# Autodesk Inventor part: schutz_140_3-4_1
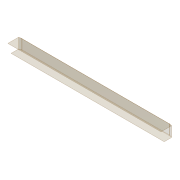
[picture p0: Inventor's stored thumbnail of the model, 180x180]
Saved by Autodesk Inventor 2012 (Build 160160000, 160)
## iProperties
Company: CAD-Verlag
Shininess: 64.0
Length Units: 11269
Angle Units: 11279
Time Units: 11290
Mass Units: 11283
Length Display Precision: 3
Angle Display Precision: 2
Compacted: True
Part Number: schutz_140_3-4_1
Document SubType Name: Sheet Metal
Created: 2004-09
Material: Standard
Designer: Greiling
Manufacturer: Standard
Standards Organization: Custom
Density: 1 g/cm^3
Sheet Metal Rule: Standard
Density: 0.0
Volumn: 0.0
Area: 0.0
PropertySet Name: Model Information
Control State: 0
Master: False
Checked Out: False
Author: Jürgen Kronas
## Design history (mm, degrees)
node "Fläche1"
  sketch "Skizze1"
    geometry: L1 (0, 168)-(2280, 168); L2 (2280, 168)-(2280, 0); L3 (2280, 0)-(0, 0); L4 (0, 0)-(0, 168); L5 (0, 218.4)-(0, -16.8) reference; L6 (-228, 0)-(2964, 0) reference; L7 (-228, 0)-(2964, 0) reference; L8 (0, -16.8)-(0, 218.4) reference; 1 further point
    constraints: 8 end point, 2 collinear, 2 parallel, 1 horizontal, 1 perpendicular
    dimensions: "d0" = 168 distance of L3.end L1.start; "d1" = 2280 distance of L1.start L1.end
sketch "Skizze2"
  geometry: L1 (0, 0)-(2280, 0) reference; L2 (0, -168)-(0, 0) reference; L3 (0, -10.718)-(40, 0); L4 (40, 0)-(0, 0); L5 (0, 0)-(0, -10.718); L6 (2280, 0)-(2280, -168) reference; L7 (2280, -10.718)-(2240, 0)
  constraints: 8 end point, 4 point on line, 2 collinear
  dimensions: "d31" = 40 distance from line of L3.end L2; "d32" = 15 deg angle of L3 L1; "d68" = 15 deg angle of L1 L7; "d69" = 40 distance from line of L7.end L6
extrude "Extrusion1" cut sketch "Skizze2" stored distance "d8" = 10; taper "d9" = 0 deg
node "Lasche1"
node "Lasche3"
node "Lasche4"
node "Lasche5"
sketch "Skizze8"
  geometry: L1 (2222.787, 117)-(2201.158, 122.796) reference; L2 (2201.158, 122.796)-(2200.381, 119.898) reference; L3 (2211.196, 117)-(2200.381, 119.898) reference; L4 (2239.605, 117)-(2239.605, 0) reference; L5 (2222.787, 117)-(2239.605, 117) reference; L6 (2238.637, 109.647)-(2211.196, 117) reference; L7 (2238.637, 109.647)-(2239.605, 109.388)
  constraints: 2 end point, 1 collinear, 1 point on line
extrude "Extrusion2" cut sketch "Skizze8" distance "d47" = 3; taper "d48" = 0 deg
node "Lasche6"
node "Lasche8"
node "Lasche9"
sketch "Skizze14"
  geometry: L1 (-2239.21, 117)-(-2279.605, 117) reference; L2 (-2279.605, 0)-(-2279.605, 117) reference; L3 (-2239.987, 119.898)-(-2278.242, 109.647) reference; L4 (-2278.242, 109.647)-(-2279.605, 109.282); L5 (-2279.605, 109.282)-(-2279.605, 117); L6 (-2250.801, 117)-(-2279.605, 109.282)
  constraints: 6 end point, 3 collinear, 3 point on line
extrude "Extrusion3" cut sketch "Skizze14" distance "d84" = 3; taper "d85" = 0 deg
sketch "Skizze15" dims "d96" = 10, "d103" = 10, "d110" = 10, "d117" = 10, "d124" = 10, "d131" = 10, "d138" = 10
  geometry: L1 (0, 0)-(-2279.605, 0) reference; L2 (-2239.21, 117)-(-2250.801, 117) reference; L3 (-2215.805, 0)-(-2215.805, 47.5); L4 (-2120.805, 47.5)-(-2120.805, 0); L5 (-2279.605, 0)-(-2279.605, 109.282) reference; L6 (-1930.055, 0)-(-1930.055, 47.5); L7 (-1835.055, 47.5)-(-1835.055, 0); L8 (-1644.305, 0)-(-1644.305, 47.5); L9 (-1549.305, 47.5)-(-1549.305, 0); L10 (-1358.555, 0)-(-1358.555, 47.5); L11 (-1263.555, 47.5)-(-1263.555, 0); L12 (-1015.655, 0)-(-1015.655, 47.5); L13 (-920.655, 47.5)-(-920.655, 0); L14 (-729.905, 0)-(-729.905, 47.5); L15 (-634.905, 47.5)-(-634.905, 0); L16 (-444.155, 0)-(-444.155, 47.5); L17 (-349.155, 47.5)-(-349.155, 0); L18 (-158.405, 0)-(-158.405, 47.5); L19 (-63.405, 47.5)-(-63.405, 0); L20 (0.395, -48)-(0.395, 109.282) reference; L21 (-1930.055, 0)-(-1835.055, 0); L22 (-1644.305, 0)-(-1549.305, 0); L23 (-1358.555, 0)-(-1263.555, 0); L24 (-1015.655, 0)-(-920.655, 0); L25 (-729.905, 0)-(-622.745, 0); L26 (-430.938, 0)-(-349.155, 0); L27 (-158.405, 0)-(-63.405, 0); L28 (-40, 117)-(-2239.21, 117) reference; L29 (-729.905, 0)-(-634.905, 0); L30 (-444.155, 0)-(-349.155, 0); A1 r 47.5 centre (-2168.305, 47.5) between (-2120.805, 47.5) and (-2215.805, 47.5); A2 r 47.5 centre (-1882.555, 47.5) between (-1835.055, 47.5) and (-1930.055, 47.5); A3 r 47.5 centre (-1596.805, 47.5) between (-1549.305, 47.5) and (-1644.305, 47.5); A4 r 47.5 centre (-1311.055, 47.5) between (-1263.555, 47.5) and (-1358.555, 47.5); A5 r 47.5 centre (-968.155, 47.5) between (-920.655, 47.5) and (-1015.655, 47.5); A6 r 47.5 centre (-682.405, 47.5) between (-634.905, 47.5) and (-729.905, 47.5); A7 r 47.5 centre (-396.655, 47.5) between (-349.155, 47.5) and (-444.155, 47.5); A8 r 47.5 centre (-110.905, 47.5) between (-63.405, 47.5) and (-158.405, 47.5)
  constraints: 50 end point, 16 point on circle, 16 tangent, 9 parallel, 8 centre point, 7 collinear, 7 horizontal, 4 point on line, 1 perpendicular, 56 other
  dimensions: "d86" = 47.5 radius of A1; "d87" = 47.5 distance from line of L1 A1.centre; "d93" = 285.75 distance of A1.centre A2.centre; "d100" = 285.75 distance of A2.centre A3.centre; "d107" = 285.75 distance of A3.centre A4.centre; "d114" = 342.9 distance of L10.end L12.end; "d121" = 285.75 distance of L12.start L14.start; "d128" = 285.75 distance of L14.start L16.start; "d135" = 285.75 distance of L16.start L18.start; "d141" = 111.3 distance from line of L5 A1.centre; "d142" = 111.3 distance from line of L20 A8.centre (derived)
extrude "Extrusion6" cut sketch "Skizze15" distance "d151" = 3; taper "d152" = 0 deg
sketch "Skizze16"
  geometry: L1 (0, 0)-(0, 157.282) reference; L2 (2280, 0)-(0, 0) reference; L3 (2280, 157.282)-(2280, 0) reference; 4 further points
  dimensions: "d153" = 15 distance from line of L2 point (40, 15); "d154" = 15 distance from line of L2 point (790, 15); "d155" = 15 distance from line of L2 point (1490, 15); "d156" = 15 distance from line of L2 point (2240, 15); "d157" = 40 distance from line of point (40, 15) L1; "d158" = 750 distance of point (790, 15) point (40, 15); "d159" = 700 distance of point (1490, 15) point (790, 15); "d160" = 750 distance of point (2240, 15) point (1490, 15); "d161" = 40 distance from line of L3 point (2240, 15) (derived)
hole "Bohrung1" sketch "Skizze16" at (40, 15), (790, 15), (1490, 15), (2240, 15) diameter "d162" = 11; stored, may be unused: countersink angle "d166" = 82 deg, drill point angle "d168" = 118 deg; dims "d163" = 6, "d164" = 4, "d165" = 2, "d167" = 8
extrude "Extrusion5" cut sketch "Skizze15" distance "d143" = 3; taper "d144" = 0 deg
node "Volumenkörper1"
node "Volumenkörpern"
node "Oberflächenkörpern"
feature "Platte1" dims "Objekthöhe" = 3
sketch "Skizze3"
  geometry: L1 (2200, 0)-(2200, 152); L2 (2200, 152)-(0, 152); 2 other entities
  constraints: 4 end point, 4 other
feature "Platte3" dims "d10" = 3 (= BreiteBiegungsfreistellung), "d12" = 6 (= MinimalRest), "d14" = 152, "d15" = 90 deg, "d16" = 3 (= Biegeradius), "Objekthöhe" = 3
feature "Biegung2" dims "d10" = 3 (= BreiteBiegungsfreistellung), "d11" = 1.5 (= TiefeBiegungsfreistellung), "d12" = 6 (= MinimalRest), "d13" = 3 (= Biegeradius), "d14" = 152, "d15" = 90 deg, "d16" = 3 (= Biegeradius), "SeamGap" = 0.01, "Objekthöhe" = 3
sketch "Skizze5"
  geometry: L1 (149, 0)-(149, 40); L2 (149, 40)-(0, 40); 2 other entities
  constraints: 4 end point, 4 other
feature "Platte5" dims "d24" = 3 (= BreiteBiegungsfreistellung), "d26" = 6 (= MinimalRest), "d28" = 40, "d29" = 15 deg, "d30" = 3 (= Biegeradius), "Objekthöhe" = 3
feature "Biegung4" dims "d24" = 3 (= BreiteBiegungsfreistellung), "d25" = 1.5 (= TiefeBiegungsfreistellung), "d26" = 6 (= MinimalRest), "d27" = 3 (= Biegeradius), "d28" = 40, "d29" = 15 deg, "d30" = 3 (= Biegeradius), "SeamGap" = 0.01, "Objekthöhe" = 3
sketch "Skizze6"
  geometry: L1 (0, -3)-(2199.605, -3); L2 (2199.605, -3)-(2199.605, 117); L3 (2199.605, 117)-(0, 117); L4 (0, 117)-(0, -3)
  constraints: 8 end point
feature "Platte6" dims "d33" = 3 (= BreiteBiegungsfreistellung), "d35" = 6 (= MinimalRest), "d37" = 120, "d38" = 90 deg, "d39" = 3 (= Biegeradius), "Objekthöhe" = 3
feature "Biegung5" dims "d33" = 3 (= BreiteBiegungsfreistellung), "d34" = 1.5 (= TiefeBiegungsfreistellung), "d35" = 6 (= MinimalRest), "d36" = 3 (= Biegeradius), "d37" = 120, "d38" = 90 deg, "d39" = 3 (= Biegeradius), "SeamGap" = 0.01, "Objekthöhe" = 3
sketch "Skizze7"
  geometry: L1 (117, 0)-(117, 40); L2 (117, 40)-(0, 40); 2 other entities
  constraints: 4 end point, 4 other
feature "Platte7" dims "d40" = 3 (= BreiteBiegungsfreistellung), "d42" = 6 (= MinimalRest), "d44" = 40, "d45" = 0, "d46" = 3 (= Biegeradius), "Objekthöhe" = 3
feature "Biegung6" dims "d40" = 3 (= BreiteBiegungsfreistellung), "d41" = 1.5 (= TiefeBiegungsfreistellung), "d42" = 6 (= MinimalRest), "d43" = 3 (= Biegeradius), "d44" = 40, "d45" = 0, "d46" = 3 (= Biegeradius), "SeamGap" = 0.01, "Objekthöhe" = 3
sketch "Skizze9"
  geometry: L1 (39.605, 0)-(39.605, 3); L2 (39.605, 3)-(0, 3); 2 other entities
  constraints: 4 end point, 4 other
feature "Platte8" dims "d49" = 3 (= BreiteBiegungsfreistellung), "d51" = 6 (= MinimalRest), "d53" = 3, "d54" = 0, "d55" = 3 (= Biegeradius), "Objekthöhe" = 3
feature "Biegung7" dims "d49" = 3 (= BreiteBiegungsfreistellung), "d50" = 1.5 (= TiefeBiegungsfreistellung), "d51" = 6 (= MinimalRest), "d52" = 3 (= Biegeradius), "d53" = 3, "d54" = 0, "d55" = 3 (= Biegeradius), "SeamGap" = 0.01, "Objekthöhe" = 3
sketch "Skizze12"
  geometry: L1 (143, 0)-(143, 40); L2 (143, 40)-(0, 40); 2 other entities
  constraints: 4 end point, 4 other
feature "Platte11" dims "d70" = 3 (= BreiteBiegungsfreistellung), "d72" = 6 (= MinimalRest), "d74" = 40, "d75" = 15 deg, "d76" = 3 (= Biegeradius), "Objekthöhe" = 3
feature "Biegung10" dims "d70" = 3 (= BreiteBiegungsfreistellung), "d71" = 1.5 (= TiefeBiegungsfreistellung), "d72" = 6 (= MinimalRest), "d73" = 3 (= Biegeradius), "d74" = 40, "d75" = 15 deg, "d76" = 3 (= Biegeradius), "SeamGap" = 0.01, "Objekthöhe" = 3
sketch "Skizze13"
  geometry: L1 (117, 0)-(117, 40); L2 (117, 40)-(0, 40); 2 other entities
  constraints: 4 end point, 4 other
feature "Platte12" dims "d77" = 3 (= BreiteBiegungsfreistellung), "d79" = 6 (= MinimalRest), "d81" = 40, "d82" = 0, "d83" = 3 (= Biegeradius), "Objekthöhe" = 3
feature "Biegung11" dims "d77" = 3 (= BreiteBiegungsfreistellung), "d78" = 1.5 (= TiefeBiegungsfreistellung), "d79" = 6 (= MinimalRest), "d80" = 3 (= Biegeradius), "d81" = 40, "d82" = 0, "d83" = 3 (= Biegeradius), "SeamGap" = 0.01, "Objekthöhe" = 3
other parameters: "Biegeradius" = 3 (= Objekthöhe), "BreiteBiegungsfreistellung" = 3 (= Objekthöhe), "TiefeBiegungsfreistellung" = 1.5 (= 0.5 x Objekthöhe), "GrößeEckenfreistellung" = 12 (= 4 x Objekthöhe), "MinimalRest" = 6 (= 2 x Objekthöhe), "Übergangsradius" = 3 (= Biegeradius), "d2" = 3 (= Biegeradius), "JacobiRadiusGröße" = 3 (= Objekthöhe), "Abstandsgröße" = 3 (= Objekthöhe)
